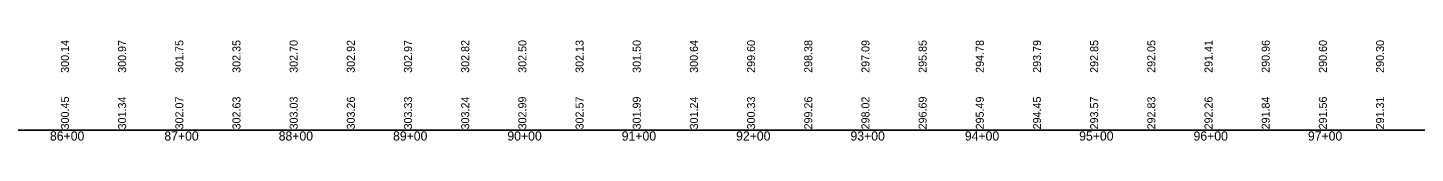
# Model space of a CAD drawing. Extents: x 1876258 to 1932803, y 754739 to 837911.
# Drawn here: x 1886926 to 1888139, y 830495 to 830583 of the extents above; entities that cross this region are included whole.
import ezdxf

# ---------------------------------------------------------------- set-up
doc = ezdxf.new("R2010")
doc.units = 0
for name, color, linetype in [('RD_DDB_StaTX', 7, 'Continuous'), ('RD_DDB_StripGrade', 7, 'Continuous'), ('RD_GPK_Profile_Cell', 7, 'Continuous')]:
    doc.layers.add(name, color=color, linetype=linetype)

msp = doc.modelspace()

# ---------------------------------------------------------------- linework, layer by layer
at = {"layer": 'RD_GPK_Profile_Cell'}
msp.add_line((1878363.1, 830504.3), (1926563.1, 830504.3), dxfattribs=at)

# ---------------------------------------------------------------- texts
at = {"layer": 'RD_DDB_StaTX'}
for s, p in [('86+00', (1886945.5, 830495.3)), ('86+00', (1886945.5, 830495.3)), ('87+00', (1887045.5, 830495.3)), ('87+00', (1887045.5, 830495.3)), ('88+00', (1887145.5, 830495.3)), ('88+00', (1887145.5, 830495.3)), ('89+00', (1887245.5, 830495.3)), ('89+00', (1887245.5, 830495.3)), ('90+00', (1887345.5, 830495.3)), ('90+00', (1887345.5, 830495.3)), ('91+00', (1887445.5, 830495.3)), ('91+00', (1887445.5, 830495.3)), ('92+00', (1887545.5, 830495.3)), ('92+00', (1887545.5, 830495.3)), ('93+00', (1887645.5, 830495.3)), ('93+00', (1887645.5, 830495.3)), ('94+00', (1887745.5, 830495.3)), ('94+00', (1887745.5, 830495.3)), ('95+00', (1887845.5, 830495.3)), ('95+00', (1887845.5, 830495.3)), ('96+00', (1887945.5, 830495.3)), ('96+00', (1887945.5, 830495.3)), ('97+00', (1888045.5, 830495.3)), ('97+00', (1888045.5, 830495.3))]:
    msp.add_text(s, height=8, dxfattribs=at).set_placement(p)
at = {"layer": 'RD_DDB_StripGrade'}
for s, p in [('300.14', (1886962.1, 830554.3)), ('300.97', (1887012.1, 830554.3)), ('301.75', (1887062.1, 830554.3)), ('302.35', (1887112.1, 830554.3)), ('302.70', (1887162.1, 830554.3)), ('302.92', (1887212.1, 830554.3)), ('302.97', (1887262.1, 830554.3)), ('302.82', (1887312.1, 830554.3)), ('302.50', (1887362.1, 830554.3)), ('302.13', (1887412.1, 830554.3)), ('301.50', (1887462.1, 830554.3)), ('300.64', (1887512.1, 830554.3)), ('299.60', (1887562.1, 830554.3)), ('298.38', (1887612.1, 830554.3)), ('297.09', (1887662.1, 830554.3)), ('295.85', (1887712.1, 830554.3)), ('294.78', (1887762.1, 830554.3)), ('293.79', (1887812.1, 830554.3)), ('292.85', (1887862.1, 830554.3)), ('292.05', (1887912.1, 830554.3)), ('291.41', (1887962.1, 830554.3)), ('290.96', (1888012.1, 830554.3)), ('290.60', (1888062.1, 830554.3)), ('290.30', (1888112.1, 830554.3)), ('300.45', (1886962.1, 830505)), ('301.34', (1887012.1, 830505)), ('302.07', (1887062.1, 830505)), ('302.63', (1887112.1, 830505)), ('303.03', (1887162.1, 830505)), ('303.26', (1887212.1, 830505)), ('303.33', (1887262.1, 830505)), ('303.24', (1887312.1, 830505)), ('302.99', (1887362.1, 830505)), ('302.57', (1887412.1, 830505)), ('301.99', (1887462.1, 830505)), ('301.24', (1887512.1, 830505)), ('300.33', (1887562.1, 830505)), ('299.26', (1887612.1, 830505)), ('298.02', (1887662.1, 830505)), ('296.69', (1887712.1, 830505)), ('295.49', (1887762.1, 830505)), ('294.45', (1887812.1, 830505)), ('293.57', (1887862.1, 830505)), ('292.83', (1887912.1, 830505)), ('292.26', (1887962.1, 830505)), ('291.84', (1888012.1, 830505)), ('291.56', (1888062.1, 830505)), ('291.31', (1888112.1, 830505))]:
    msp.add_text(s, height=7, rotation=90, dxfattribs=at).set_placement(p)

doc.saveas('drawing.dxf')
